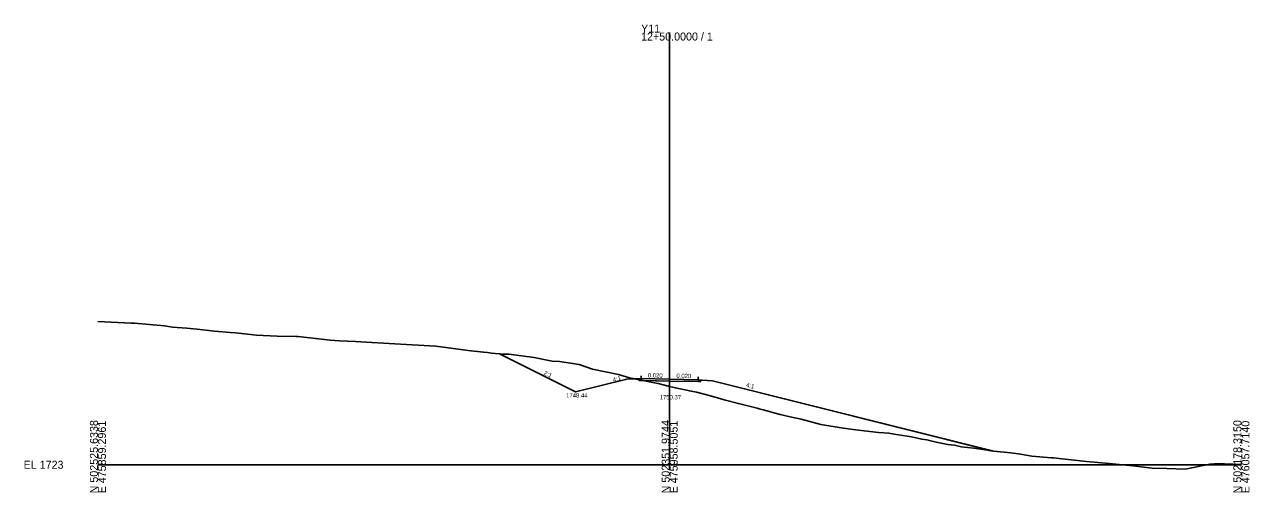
# Model space of a CAD drawing. Extents: x -76 to 353, y -10 to 8186.
# Drawn here: x -75.7 to 352.8, y 4990.3 to 5153.9 of the extents above; entities that cross this region are included whole.
import ezdxf

# ---------------------------------------------------------------- set-up
doc = ezdxf.new("R2010")
doc.units = 0
for name, color, linetype in [('Exist Cross Section Cell', 7, 'Continuous'), ('Exist XS Center Line Elevation Label', 7, 'Continuous'), ('Exist XS Ground Line', 7, 'Continuous'), ('Prop XS Ditch Slope Text', 7, 'Continuous'), ('Prop XS Ditch Standard Text', 7, 'Continuous'), ('Prop XS Dump Level', 7, 'Continuous'), ('Prop XS Earthwork Shape', 7, 'Continuous'), ('Prop XS EOT Tick Mark', 7, 'Continuous'), ('Prop XS Finish Grade', 7, 'Continuous'), ('Prop XS Finish Grade Earthwork', 7, 'Continuous'), ('Prop XS Finish Grade Pavement', 7, 'Continuous'), ('Prop XS Hydro Fill Slope Data', 7, 'Continuous'), ('Prop XS Hydro Typical Ditch Data', 7, 'Continuous'), ('Prop XS Pvmt Edge Slope', 7, 'Continuous'), ('Prop XS SE Text', 7, 'Continuous'), ('Prop XS Shoulder Borrow Shape', 7, 'Continuous'), ('Prop XS Side Slope Text', 7, 'Continuous'), ('Prop XS Subgrade Earthwork', 7, 'Continuous'), ('Scratch_Level_6', 7, 'Continuous')]:
    doc.layers.add(name, color=color, linetype=linetype)

msp = doc.modelspace()

# ---------------------------------------------------------------- linework, layer by layer
at = {"layer": 'Exist Cross Section Cell'}
for p, q in [((150, 5000), (150, 5151.1)), ((-50, 5000), (150, 5000)), ((150, 5000), (350, 5000))]:
    msp.add_line(p, q, dxfattribs=at)
at = {"layer": 'Exist XS Ground Line'}
msp.add_lwpolyline([(-50, 5050.07), (-40.66, 5049.63), (-38.36, 5049.52), (-37.25, 5049.44), (-26.77, 5048.54), (-23.91, 5048.15), (-18.9, 5047.72), (-16.58, 5047.49), (-15.25, 5047.38), (-9.25, 5046.73), (-3.73, 5046.28), (-1.91, 5046.16), (1.26, 5045.78), (5.42, 5045.33), (7.79, 5045.2), (12.75, 5044.92), (19.31, 5044.86), (20.08, 5044.85), (31.29, 5043.5), (34.53, 5043.37), (40.12, 5043.14), (43.78, 5042.89), (59.97, 5041.96), (68.15, 5041.45), (79.48, 5039.92), (84.83, 5039.34), (86.27, 5039.24), (87.71, 5039.03), (90.39, 5038.76), (91.44, 5038.71), (93.75, 5038.64), (102.56, 5037.46), (106.52, 5036.72), (108.9, 5036.23), (111.46, 5036.09), (118.34, 5035.01), (122.98, 5033.44), (132.07, 5031.52), (135.98, 5030.41), (142.4, 5029.12), (144.71, 5028.67), (146.02, 5028.36), (150, 5027.37), (152.04, 5026.86), (157.54, 5025.77), (159.37, 5025.32), (162.57, 5024.54), (166.7, 5023.39), (169.06, 5022.73), (174.03, 5021.37), (180.58, 5019.77), (181.36, 5019.6), (182.73, 5019.24), (188.69, 5017.58), (192.1, 5016.78), (196.02, 5015.89), (202.9, 5014.04), (203.61, 5013.9), (210.68, 5012.8), (215.13, 5012.18), (218.01, 5011.82), (223.06, 5011.29), (226.65, 5011.06), (228.59, 5010.68), (234.65, 5009.71), (238.17, 5008.89), (240.01, 5008.69), (243.22, 5007.94), (247.34, 5007.13), (249.69, 5006.81), (252.02, 5006.29), (256.41, 5005.75), (261.21, 5005.08), (263.39, 5004.75), (269.33, 5004.2), (272.73, 5003.65), (276.66, 5003.05), (283.55, 5002.44), (284.25, 5002.38), (285.18, 5002.28), (295.77, 5001.09), (303.71, 5000.43), (307.29, 5000.05), (312.05, 4999.6), (318.8, 4998.82), (323.88, 4998.69), (330.32, 4998.5), (338.92, 5000.17), (341.84, 5000.41), (344.04, 5000.38), (350, 5000.09)], dxfattribs=at)
at = {"layer": 'Prop XS Dump Level'}
for p, q in [((140, 5030.12), (150, 5029.92)), ((150, 5029.92), (160, 5029.72))]:
    msp.add_line(p, q, dxfattribs=at)
at = {"layer": 'Prop XS Earthwork Shape'}
for points in [[(106.52, 5036.72), (108.9, 5036.23), (111.46, 5036.09), (118.34, 5035.01), (122.98, 5033.44), (132.07, 5031.52), (135.98, 5030.41), (137.87, 5030.03), (135, 5029.92), (117.1, 5025.44), (90.47, 5038.76), (91.44, 5038.71), (93.75, 5038.64), (102.56, 5037.46)], [(138.74, 5030.06), (137.87, 5030.03), (139, 5029.8)], [(140, 5029.45), (139.35, 5029.46), (139, 5029.8), (140.86, 5029.43)], [(150, 5027.37), (152.04, 5026.86), (157.54, 5025.77), (159.37, 5025.32), (162.57, 5024.54), (166.7, 5023.39), (169.06, 5022.73), (174.03, 5021.37), (180.58, 5019.77), (181.36, 5019.6), (182.73, 5019.24), (188.69, 5017.58), (192.1, 5016.78), (196.02, 5015.89), (202.9, 5014.04), (203.61, 5013.9), (210.68, 5012.8), (215.13, 5012.18), (218.01, 5011.82), (223.06, 5011.29), (226.65, 5011.06), (228.59, 5010.68), (234.65, 5009.71), (238.17, 5008.89), (240.01, 5008.69), (243.22, 5007.94), (247.34, 5007.13), (249.69, 5006.81), (252.02, 5006.29), (256.41, 5005.75), (261.21, 5005.08), (263.07, 5004.8), (165, 5029.32), (161.26, 5029.61), (160.68, 5029.03), (160, 5029.05), (150, 5029.25), (140.86, 5029.43), (142.4, 5029.12), (144.71, 5028.67), (146.02, 5028.36)]]:
    msp.add_lwpolyline(points, close=True, dxfattribs=at)
at = {"layer": 'Prop XS EOT Tick Mark'}
for p, q in [((140, 5030.12), (140, 5031.12)), ((160, 5029.72), (160, 5030.72))]:
    msp.add_line(p, q, dxfattribs=at)
at = {"layer": 'Prop XS Finish Grade'}
for p, q in [((140, 5030.12), (138.74, 5030.06)), ((160, 5029.72), (161.26, 5029.61))]:
    msp.add_line(p, q, dxfattribs=at)
at = {"layer": 'Prop XS Finish Grade Earthwork'}
for p, q in [((117.1, 5025.44), (90.47, 5038.76)), ((135, 5029.92), (117.1, 5025.44)), ((138.74, 5030.06), (135, 5029.92)), ((161.26, 5029.61), (165, 5029.32)), ((165, 5029.32), (263.07, 5004.8))]:
    msp.add_line(p, q, dxfattribs=at)
at = {"layer": 'Prop XS Finish Grade Pavement'}
for p, q in [((140, 5030.12), (150, 5029.92)), ((150, 5029.92), (160, 5029.72))]:
    msp.add_line(p, q, dxfattribs=at)
at = {"layer": 'Prop XS Hydro Fill Slope Data'}
msp.add_line((165, 5029.32), (263.07, 5004.8), dxfattribs=at)
at = {"layer": 'Prop XS Hydro Typical Ditch Data'}
msp.add_line((135, 5029.92), (127, 5027.92), dxfattribs=at)
at = {"layer": 'Prop XS Pvmt Edge Slope'}
for p, q in [((140, 5030.12), (139.35, 5029.46)), ((160, 5029.72), (160.68, 5029.03))]:
    msp.add_line(p, q, dxfattribs=at)
at = {"layer": 'Prop XS Shoulder Borrow Shape'}
for points in [[(140, 5030.12), (139.35, 5029.46), (138.74, 5030.06)], [(140, 5030.12), (139.35, 5029.46), (138.74, 5030.06)], [(160.68, 5029.03), (161.26, 5029.61), (160, 5029.72)], [(160.68, 5029.03), (161.26, 5029.61), (160, 5029.72)]]:
    msp.add_lwpolyline(points, close=True, dxfattribs=at)
at = {"layer": 'Prop XS Subgrade Earthwork'}
for p, q in [((139.35, 5029.46), (138.74, 5030.06)), ((140, 5029.45), (139.35, 5029.46)), ((150, 5029.25), (140, 5029.45)), ((160, 5029.05), (150, 5029.25)), ((160, 5029.05), (160.68, 5029.03)), ((160.68, 5029.03), (161.26, 5029.61))]:
    msp.add_line(p, q, dxfattribs=at)
at = {"layer": 'Scratch_Level_6'}
msp.add_line((165, 5029.34), (263.36, 5004.75), dxfattribs=at)

# ---------------------------------------------------------------- texts
at = {"layer": 'Exist Cross Section Cell'}
for s, p in [('Y11', (140, 5151.1)), ('12+50.0000 / 1', (140, 5148.3)), ('EL 1723', (-76, 4998.6))]:
    msp.add_text(s, height=2.8, dxfattribs=at).set_placement(p)
for s, p in [('N 502525.6338', (-50, 4990)), ('E 475859.2961', (-47.2, 4990)), ('N 502351.9744', (150, 4990)), ('E 475958.5051', (152.8, 4990)), ('N 502178.3150', (350, 4990)), ('E 476057.7140', (352.8, 4990))]:
    msp.add_text(s, height=2.8, rotation=90, dxfattribs=at).set_placement(p)
at = {"layer": 'Exist XS Center Line Elevation Label'}
msp.add_text('1750.37', height=1.5, dxfattribs=at).set_placement((146.5, 5022.87))
at = {"layer": 'Prop XS Ditch Slope Text'}
msp.add_text('4:1', height=1.5, rotation=14.0362, dxfattribs=at).set_placement((130.32, 5028.94))
at = {"layer": 'Prop XS Ditch Standard Text'}
msp.add_text('1748.44', height=1.5, dxfattribs=at).set_placement((113.79, 5023.52))
at = {"layer": 'Prop XS Dump Level'}
for p in [(135, 5029.88), (165, 5029.28)]:
    msp.add_text('Case1', height=0.04, dxfattribs=at).set_placement(p)
at = {"layer": 'Prop XS SE Text'}
for p in [(142.35, 5030.57), (152.35, 5030.37)]:
    msp.add_text('0.020', height=1.5, rotation=358.8542, dxfattribs=at).set_placement(p)
at = {"layer": 'Prop XS Side Slope Text'}
for s, rotation, p in [('2:1', 333.4349, (105.76, 5031.64)), ('4:1', 345.9638, (176.65, 5027.23))]:
    msp.add_text(s, height=1.5, rotation=rotation, dxfattribs=at).set_placement(p)

doc.saveas('drawing.dxf')
